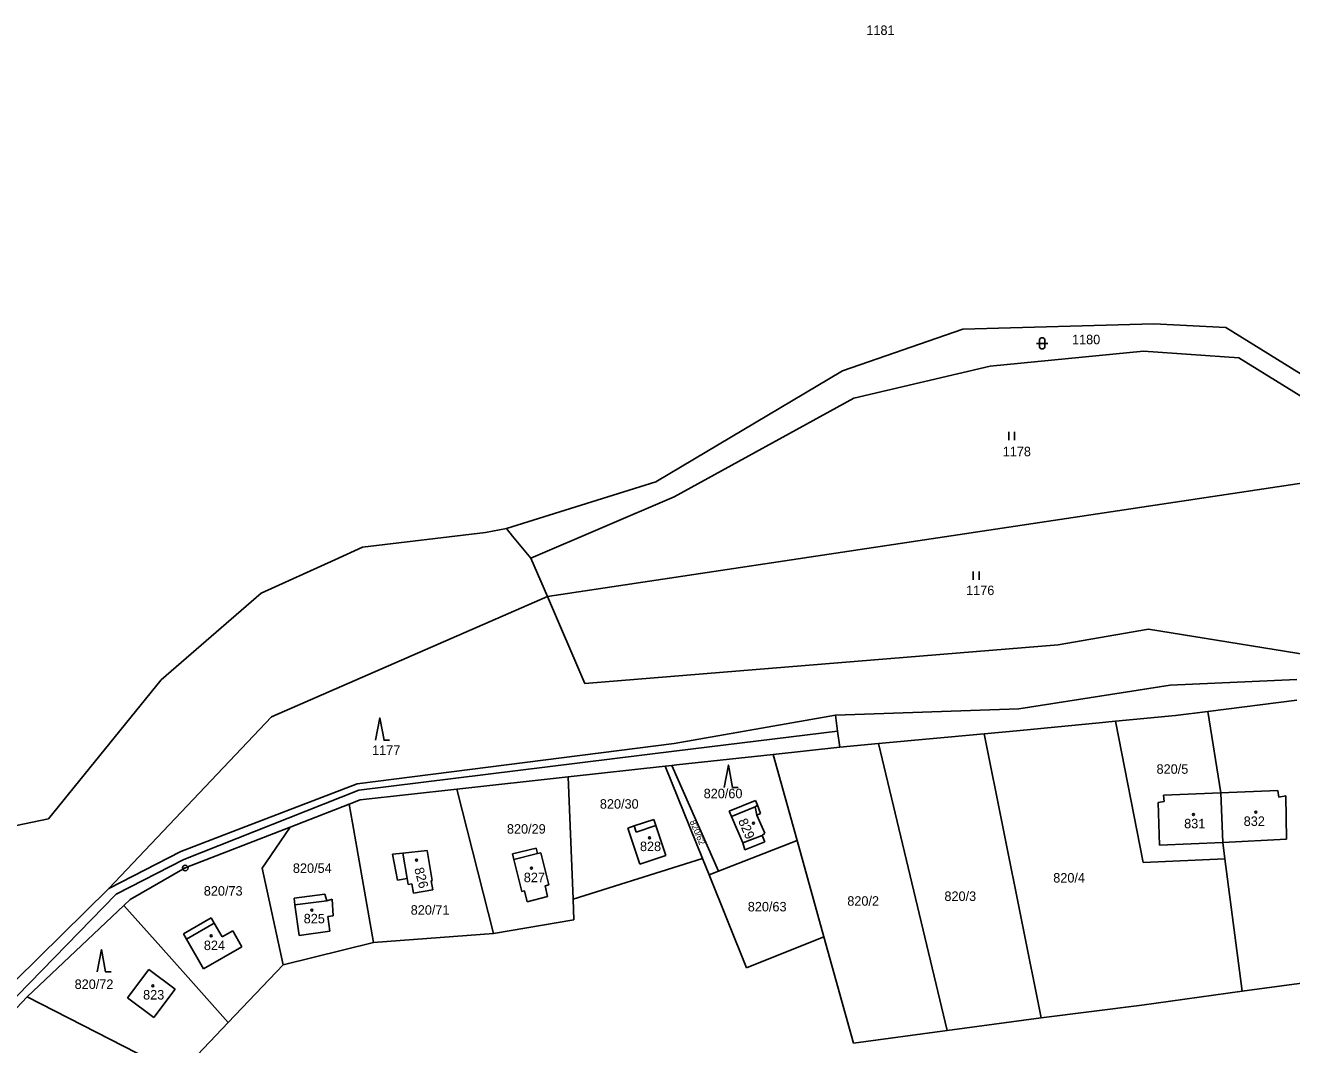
# Model space of a CAD drawing. Extents: x -779596 to -776743, y -1030330 to -1024513.
# Drawn here: x -778843.2 to -778616.1, y -1026621.2 to -1026438.3 of the extents above; entities that cross this region are included whole.
import ezdxf

# ---------------------------------------------------------------- set-up
doc = ezdxf.new("R2010")
doc.units = 0
for name, color, linetype in [('hranice parcel', 7, 'Continuous'), ('hranice vnitřní', 7, 'Continuous'), ('K_Ú_ hranice', 7, 'Continuous'), ('kultura', 7, 'Continuous'), ('Kód', 7, 'Continuous'), ('č_ parcel šipka', 7, 'Continuous'), ('č_pacel stav_', 7, 'Continuous'), ('č_parcel poz_', 7, 'Continuous')]:
    doc.layers.add(name, color=color, linetype=linetype)

msp = doc.modelspace()

# ---------------------------------------------------------------- linework, layer by layer
at = {"layer": 'hranice parcel'}
for points in [[(-778696.66, -1026500.33), (-778675.09, -1026492.83)], [(-778675.09, -1026492.83), (-778640.8, -1026491.85)], [(-778640.8, -1026491.85), (-778627.93, -1026492.53)], [(-778627.93, -1026492.53), (-778622.92, -1026495.63)], [(-778622.92, -1026495.63), (-778599.16, -1026510.34)], [(-778670.17, -1026499.5), (-778642.67, -1026496.8)], [(-778642.67, -1026496.8), (-778625.6, -1026497.98)], [(-778694.61, -1026505.19), (-778670.17, -1026499.5)], [(-778625.6, -1026497.98), (-778600.07, -1026513.74)], [(-778730.15, -1026520.2), (-778696.66, -1026500.33)], [(-778726.84, -1026522.9), (-778694.61, -1026505.19)], [(-778749.6, -1026540.78), (-778598, -1026518)], [(-778756.96, -1026528.59), (-778730.15, -1026520.2)], [(-778752.55, -1026533.94), (-778726.84, -1026522.9)], [(-778782.74, -1026531.95), (-778760.72, -1026529.29)], [(-778760.72, -1026529.29), (-778756.96, -1026528.59)], [(-778756.96, -1026528.59), (-778755.84, -1026529.95)], [(-778787.72, -1026534.2), (-778782.74, -1026531.95)], [(-778755.84, -1026529.95), (-778752.55, -1026533.94)], [(-778800.95, -1026540.19), (-778787.72, -1026534.2)], [(-778752.55, -1026533.94), (-778749.6, -1026540.78)], [(-778818.89, -1026555.76), (-778800.95, -1026540.19)], [(-778799.07, -1026562.38), (-778749.6, -1026540.78)], [(-778749.6, -1026540.78), (-778742.89, -1026556.4)], [(-778658.01, -1026549.46), (-778641.78, -1026546.68)], [(-778641.78, -1026546.68), (-778607.07, -1026552.28)], [(-778742.89, -1026556.4), (-778658.01, -1026549.46)], [(-778839.09, -1026580.71), (-778818.89, -1026555.76)], [(-778636.94, -1026562.16), (-778631.14, -1026561.43)], [(-778631.14, -1026561.43), (-778615.17, -1026559.41)], [(-778628.83, -1026576.04), (-778631.14, -1026561.43)], [(-778828.29, -1026593.17), (-778799.07, -1026562.38)], [(-778697.95, -1026562.06), (-778697.56, -1026564.93)], [(-778664.82, -1026564.81), (-778650.66, -1026563.46)], [(-778650.66, -1026563.46), (-778647.69, -1026563.18)], [(-778647.69, -1026563.18), (-778636.94, -1026562.16)], [(-778647.69, -1026563.18), (-778642.74, -1026588.51)], [(-778726.39, -1026568.5), (-778697.56, -1026564.93)], [(-778697.56, -1026564.93), (-778697.17, -1026567.83)], [(-778690.2, -1026567.18), (-778671.29, -1026565.41)], [(-778671.29, -1026565.41), (-778664.82, -1026564.81)], [(-778671.29, -1026565.41), (-778661.03, -1026616.39)], [(-778709.09, -1026569.12), (-778697.17, -1026567.83)], [(-778697.17, -1026567.83), (-778690.2, -1026567.18)], [(-778690.2, -1026567.18), (-778677.87, -1026618.64)], [(-778783.41, -1026575.52), (-778726.39, -1026568.5)], [(-778709.09, -1026569.12), (-778726.47, -1026571.01)], [(-778704.81, -1026584.54), (-778709.09, -1026569.12)], [(-778728.46, -1026571.23), (-778745.86, -1026573.16)], [(-778728.46, -1026571.23), (-778727.27, -1026571.1)], [(-778721.79, -1026587.81), (-778728.46, -1026571.23)], [(-778727.27, -1026571.1), (-778726.47, -1026571.01)], [(-778727.27, -1026571.1), (-778718.89, -1026590.07)], [(-778745.86, -1026573.16), (-778765.85, -1026575.37)], [(-778744.98, -1026595.12), (-778745.86, -1026573.16)], [(-778814.81, -1026587.99), (-778783.41, -1026575.52)], [(-778785.13, -1026578.06), (-778783.16, -1026577.29)], [(-778765.85, -1026575.37), (-778783.16, -1026577.29)], [(-778765.85, -1026575.37), (-778759.3, -1026601.24)], [(-778717.02, -1026579.28), (-778712.27, -1026577.4)], [(-778712.27, -1026577.4), (-778711.9, -1026578.26)], [(-778639.09, -1026576.46), (-778628.83, -1026576.04)], [(-778639, -1026577.59), (-778639.09, -1026576.46)], [(-778628.83, -1026576.04), (-778618.58, -1026575.61)], [(-778628.83, -1026576.04), (-778628.47, -1026584.91)], [(-778618.58, -1026575.61), (-778618.38, -1026576.78)], [(-778618.38, -1026576.78), (-778617.13, -1026576.58)], [(-778617.13, -1026576.58), (-778617.04, -1026584.34)], [(-778795.77, -1026582.19), (-778785.13, -1026578.06)], [(-778785.13, -1026578.06), (-778784.55, -1026581.39)], [(-778716.59, -1026580.28), (-778717.02, -1026579.28)], [(-778711.9, -1026578.26), (-778711.35, -1026579.72)], [(-778640.07, -1026577.76), (-778639, -1026577.59)], [(-778639.83, -1026585.38), (-778640.07, -1026577.76)], [(-778852.35, -1026583.42), (-778839.09, -1026580.71)], [(-778784.55, -1026581.39), (-778780.79, -1026602.89)], [(-778734.04, -1026581.96), (-778730.5, -1026580.8)], [(-778730.14, -1026581.9), (-778730.5, -1026580.8)], [(-778730.14, -1026581.9), (-778728.36, -1026587.29)], [(-778714.56, -1026584.98), (-778716.59, -1026580.28)], [(-778711.35, -1026579.72), (-778712.05, -1026580)], [(-778712.05, -1026580), (-778710.63, -1026583.28)], [(-778814.56, -1026589.5), (-778795.77, -1026582.19)], [(-778795.77, -1026582.19), (-778797.56, -1026584.83)], [(-778734.04, -1026581.96), (-778735.2, -1026582.34)], [(-778733.05, -1026588.84), (-778735.2, -1026582.34)], [(-778711.07, -1026583.67), (-778710.63, -1026583.28)], [(-778710.62, -1026584.8), (-778711.07, -1026583.67)], [(-778797.56, -1026584.83), (-778800.75, -1026589.56)], [(-778775.56, -1026586.82), (-778771.17, -1026586.34)], [(-778771.17, -1026586.34), (-778770.28, -1026591.75)], [(-778755.86, -1026586.97), (-778751.63, -1026585.93)], [(-778751.63, -1026585.93), (-778751.38, -1026586.92)], [(-778718.89, -1026590.07), (-778704.81, -1026584.54)], [(-778714.56, -1026584.98), (-778714.21, -1026586.22)], [(-778714.21, -1026586.22), (-778710.62, -1026584.8)], [(-778699.99, -1026601.88), (-778704.81, -1026584.54)], [(-778628.47, -1026584.91), (-778639.83, -1026585.38)], [(-778617.04, -1026584.34), (-778628.47, -1026584.91)], [(-778628.47, -1026584.91), (-778628.08, -1026587.88)], [(-778826.94, -1026594.17), (-778814.81, -1026587.99)], [(-778775.56, -1026586.82), (-778777.38, -1026587.02)], [(-778776.5, -1026591.66), (-778777.38, -1026587.02)], [(-778755.62, -1026587.98), (-778755.86, -1026586.97)], [(-778754.2, -1026593.74), (-778755.62, -1026587.98)], [(-778751.38, -1026586.92), (-778750.76, -1026586.76)], [(-778750.76, -1026586.76), (-778749.34, -1026592.55)], [(-778744.98, -1026595.12), (-778721.79, -1026587.81)], [(-778728.36, -1026587.29), (-778733.05, -1026588.84)], [(-778721.79, -1026587.81), (-778720.61, -1026590.75)], [(-778628.08, -1026587.88), (-778642.74, -1026588.51)], [(-778624.99, -1026611.59), (-778628.08, -1026587.88)], [(-778814.56, -1026589.5), (-778824.45, -1026595.13)], [(-778800.75, -1026589.56), (-778796.97, -1026606.9)], [(-778720.61, -1026590.75), (-778718.89, -1026590.07)], [(-778720.61, -1026590.75), (-778713.89, -1026607.44)], [(-778774.74, -1026591.37), (-778776.5, -1026591.66)], [(-778774.56, -1026592.46), (-778774.74, -1026591.37)], [(-778773.89, -1026592.35), (-778774.56, -1026592.46)], [(-778773.62, -1026593.99), (-778773.89, -1026592.35)], [(-778770.28, -1026591.75), (-778770.45, -1026591.78)], [(-778770.45, -1026591.78), (-778770.18, -1026593.42)], [(-778749.34, -1026592.55), (-778750.03, -1026592.72)], [(-778750.03, -1026592.72), (-778749.56, -1026594.64)], [(-778855.83, -1026623.8), (-778826.94, -1026594.17)], [(-778825.59, -1026596.21), (-778824.45, -1026595.13)], [(-778795.04, -1026594.92), (-778789.54, -1026594.17)], [(-778794.88, -1026596.11), (-778795.04, -1026594.92)], [(-778789.54, -1026594.17), (-778789.19, -1026595.39)], [(-778789.19, -1026595.39), (-778788.21, -1026595.1)], [(-778788.21, -1026595.1), (-778788, -1026598.08)], [(-778770.18, -1026593.42), (-778773.62, -1026593.99)], [(-778753.72, -1026593.62), (-778754.2, -1026593.74)], [(-778753.24, -1026595.57), (-778753.72, -1026593.62)], [(-778749.56, -1026594.64), (-778753.24, -1026595.57)], [(-778744.84, -1026598.82), (-778744.98, -1026595.12)], [(-778842.89, -1026612.63), (-778825.59, -1026596.21)], [(-778825.59, -1026596.21), (-778818.96, -1026603.65)], [(-778794.13, -1026601.6), (-778794.88, -1026596.11)], [(-778814.87, -1026601.31), (-778809.89, -1026598.46)], [(-778809.35, -1026599.41), (-778809.89, -1026598.46)], [(-778809.35, -1026599.41), (-778807.94, -1026601.87)], [(-778788, -1026598.08), (-778788.99, -1026598.22)], [(-778788.99, -1026598.22), (-778788.63, -1026600.85)], [(-778759.3, -1026601.24), (-778744.84, -1026598.82)], [(-778814.32, -1026602.27), (-778814.87, -1026601.31)], [(-778811.29, -1026607.57), (-778814.32, -1026602.27)], [(-778807.94, -1026601.87), (-778806.05, -1026600.79)], [(-778806.05, -1026600.79), (-778804.42, -1026603.64)], [(-778788.63, -1026600.85), (-778794.13, -1026601.6)], [(-778780.79, -1026602.89), (-778759.3, -1026601.24)], [(-778713.89, -1026607.44), (-778699.99, -1026601.88)], [(-778699.99, -1026601.88), (-778694.71, -1026620.9)], [(-778818.96, -1026603.65), (-778814.05, -1026609.15)], [(-778804.42, -1026603.64), (-778811.29, -1026607.57)], [(-778780.79, -1026602.89), (-778796.97, -1026606.9)], [(-778796.97, -1026606.9), (-778806.84, -1026617.24)], [(-778824.91, -1026612.81), (-778821.1, -1026607.7)], [(-778821.1, -1026607.7), (-778816.36, -1026611.24)], [(-778814.05, -1026609.15), (-778806.84, -1026617.24)], [(-778594.29, -1026607.49), (-778624.99, -1026611.59)], [(-778816.36, -1026611.24), (-778820.17, -1026616.34)], [(-778842.89, -1026612.63), (-778855.24, -1026625.68)], [(-778842.89, -1026612.63), (-778815.73, -1026626.55)], [(-778820.17, -1026616.34), (-778824.91, -1026612.81)], [(-778643.01, -1026614.13), (-778624.99, -1026611.59)], [(-778643.01, -1026614.13), (-778661.03, -1026616.39)], [(-778806.84, -1026617.24), (-778815.73, -1026626.55)], [(-778661.03, -1026616.39), (-778677.87, -1026618.64)], [(-778694.71, -1026620.9), (-778677.87, -1026618.64)]]:
    msp.add_lwpolyline(points, dxfattribs=at)
at = {"layer": 'hranice vnitřní'}
for points in [[(-778716.59, -1026580.28), (-778712.32, -1026578.51)], [(-778711.9, -1026578.26), (-778712.32, -1026578.51)], [(-778712.32, -1026578.51), (-778712.05, -1026580)], [(-778733.68, -1026583.05), (-778730.14, -1026581.9)], [(-778734.04, -1026581.96), (-778733.68, -1026583.05)], [(-778714.56, -1026584.98), (-778711.07, -1026583.67)], [(-778774.74, -1026591.37), (-778775.56, -1026586.82)], [(-778755.62, -1026587.98), (-778751.38, -1026586.92)], [(-778794.88, -1026596.11), (-778789.19, -1026595.39)], [(-778814.32, -1026602.27), (-778809.35, -1026599.41)]]:
    msp.add_lwpolyline(points, dxfattribs=at)
at = {"layer": 'K_Ú_ hranice'}
for points in [[(-778665.05, -1026560.94), (-778637.9, -1026556.7)], [(-778637.9, -1026556.7), (-778615.17, -1026555.71)], [(-778697.95, -1026562.06), (-778665.05, -1026560.94)], [(-778726.86, -1026567.19), (-778697.95, -1026562.06)], [(-778783.71, -1026574.38), (-778726.86, -1026567.19)], [(-778804.48, -1026582.35), (-778783.71, -1026574.38)], [(-778815.36, -1026586.53), (-778804.48, -1026582.35)], [(-778828.29, -1026593.17), (-778815.36, -1026586.53)], [(-778845.03, -1026609.69), (-778828.29, -1026593.17)]]:
    msp.add_lwpolyline(points, dxfattribs=at)
at = {"layer": 'kultura'}
for points in [[(-778661.85, -1026495.38), (-778659.85, -1026495.38)], [(-778661.35, -1026495.88), (-778661.35, -1026494.88)], [(-778660.35, -1026494.88), (-778660.35, -1026495.88)], [(-778666.827, -1026512.725), (-778666.827, -1026511.225)], [(-778665.793, -1026512.725), (-778665.793, -1026511.225)], [(-778673.217, -1026537.815), (-778673.217, -1026536.315)], [(-778672.183, -1026537.815), (-778672.183, -1026536.315)], [(-778780.41, -1026566.58), (-778779.66, -1026562.58), (-778778.91, -1026566.58), (-778777.91, -1026566.58)], [(-778717.89, -1026575.04), (-778717.14, -1026571.04), (-778716.39, -1026575.04), (-778715.39, -1026575.04)], [(-778830.36, -1026608.15), (-778829.61, -1026604.15), (-778828.86, -1026608.15), (-778827.86, -1026608.15)]]:
    msp.add_lwpolyline(points, dxfattribs=at)
for centre in [(-778622.55, -1026579.48), (-778712.66, -1026581.47), (-778633.73, -1026579.91), (-778731.28, -1026584.08), (-778773.07, -1026588.09), (-778752.48, -1026589.54), (-778791.83, -1026597.05), (-778809.91, -1026601.68), (-778820.35, -1026610.66)]:
    msp.add_circle(centre, 0.175, dxfattribs=at)
for centre, start, end in [((-778660.85, -1026494.88), 0.101, 180.00143), ((-778660.85, -1026495.88), 180.10243, 0.00286)]:
    msp.add_arc(centre, 0.5, start, end, dxfattribs=at)
at = {"layer": 'Kód'}
for radius in [0.5, 0.032]:
    msp.add_circle((-778814.56, -1026589.5), radius, dxfattribs=at)

# ---------------------------------------------------------------- texts
at = {"layer": 'č_ parcel šipka'}
msp.add_text('1181', height=1.7, dxfattribs=at).set_placement((-778692.39, -1026440.05))
at = {"layer": 'č_pacel stav_'}
for s, rotation, p in [('829', 293.70234, (-778715.427, -1026581.052)), ('826', 284.50226, (-778773.497, -1026589.633))]:
    msp.add_text(s, height=1.7, rotation=rotation, dxfattribs=at).set_placement(p)
for s, p in [('831', (-778635.39, -1026582.38)), ('832', (-778624.71, -1026581.95)), ('828', (-778733, -1026586.47)), ('827', (-778753.84, -1026592.05)), ('825', (-778793.31, -1026599.43)), ('823', (-778822.12, -1026613.1))]:
    msp.add_text(s, height=1.7, dxfattribs=at).set_placement(p)
at = {"layer": 'č_parcel poz_'}
for s, p in [('1180', (-778655.5, -1026495.54)), ('1178', (-778667.93, -1026515.63)), ('1176', (-778674.5, -1026540.54)), ('1177', (-778781.05, -1026569.22)), ('820/5', (-778640.34, -1026572.6)), ('820/30', (-778740.19, -1026578.86)), ('820/60', (-778721.57, -1026576.99)), ('820/29', (-778756.86, -1026583.34)), ('820/54', (-778795.25, -1026590.38)), ('820/4', (-778658.87, -1026592.11)), ('820/73', (-778811.23, -1026594.46)), ('820/63', (-778713.66, -1026597.29)), ('820/2', (-778695.81, -1026596.27)), ('820/3', (-778678.39, -1026595.41)), ('820/71', (-778774.12, -1026597.88)), ('824', (-778811.219, -1026604.23)), ('820/72', (-778834.4, -1026611.2))]:
    msp.add_text(s, height=1.7, dxfattribs=at).set_placement(p)
msp.add_text('820/62', height=1.14, rotation=293.20233, dxfattribs=at).set_placement((-778724.118, -1026581.205))

doc.saveas('drawing.dxf')
